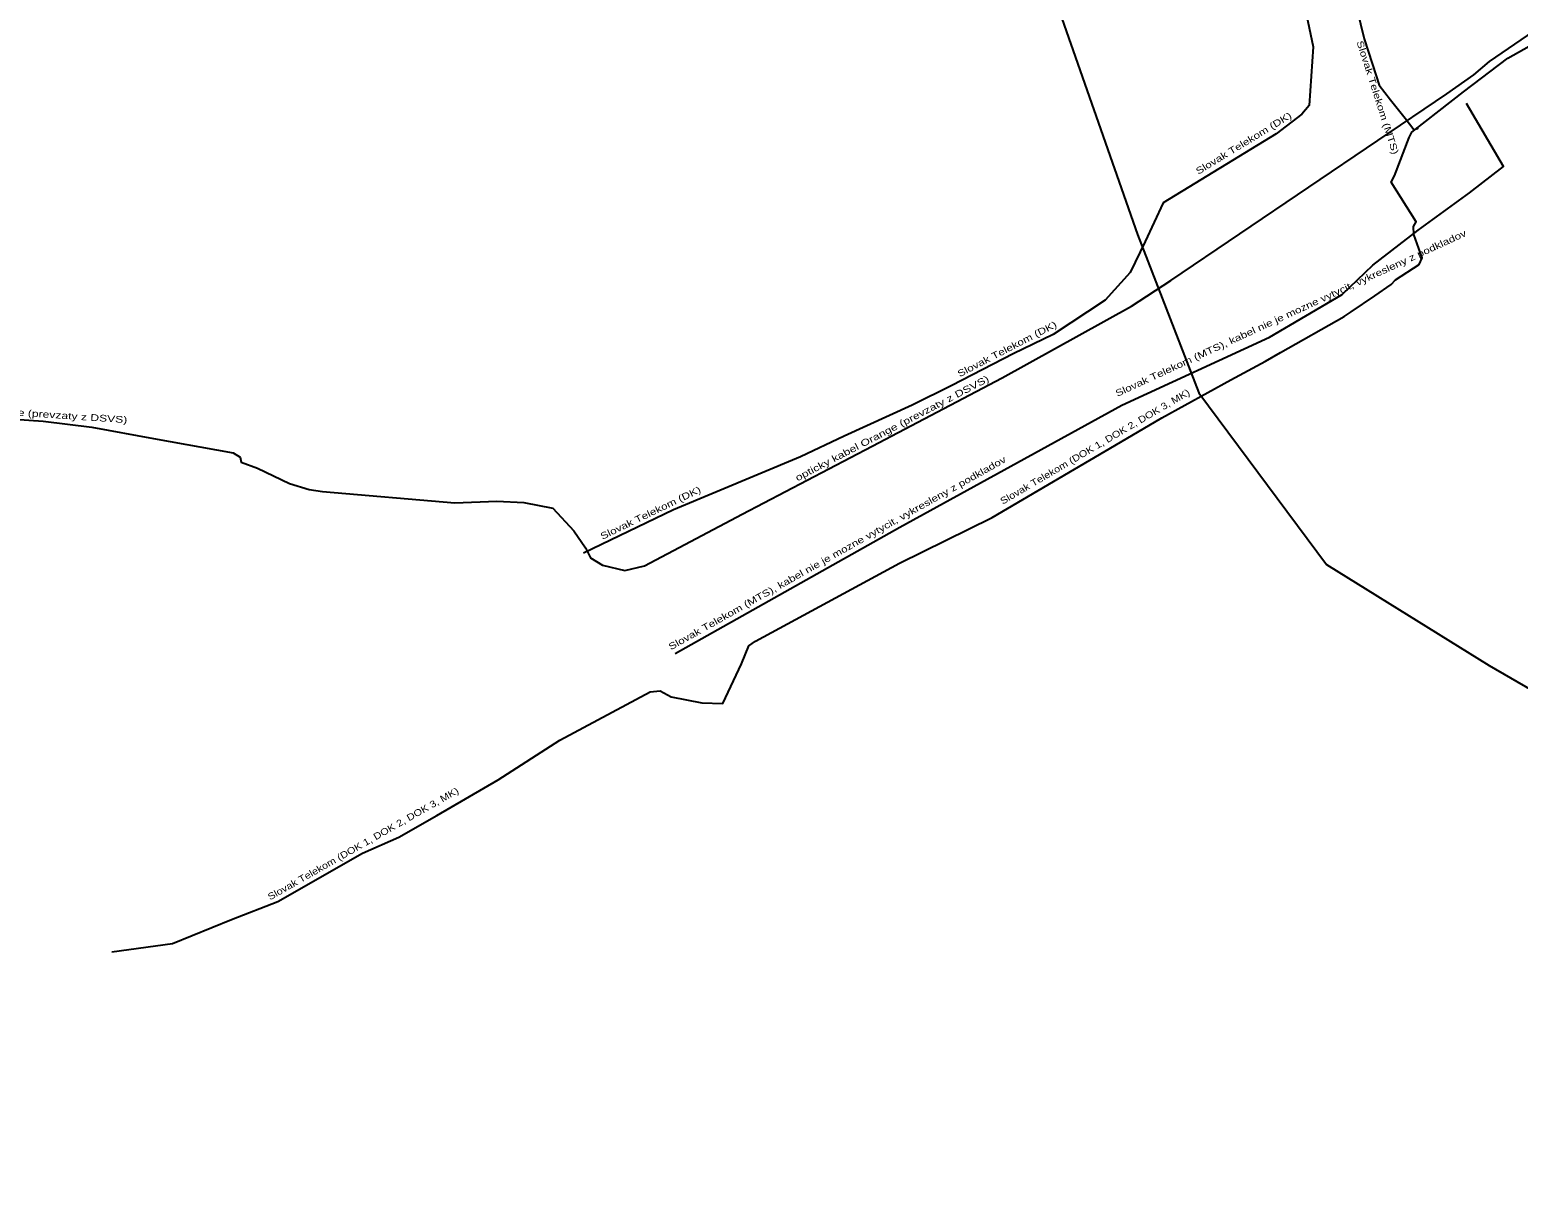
# Model space of a CAD drawing. Extents: x -347142 to -339829, y -1273273 to -1271592.
# Drawn here: x -344698.9 to -344255.5, y -1273148.9 to -1272799.8 of the extents above; entities that cross this region are included whole.
import ezdxf

# ---------------------------------------------------------------- set-up
doc = ezdxf.new("R2010")
doc.units = 0
doc.header["$LTSCALE"] = 0.8
doc.layers.add('12', color=7, linetype='Continuous', lineweight=25)
doc.layers.add('22', color=7, linetype='Continuous', lineweight=25)
doc.layers.add('60', color=7, linetype='Continuous')

msp = doc.modelspace()

# ---------------------------------------------------------------- linework, layer by layer
at = {"layer": '12'}
for points in [[(-344271.831, -1272818.294), (-344258.591, -1272808.281), (-344242.704, -1272799.364), (-344235.379, -1272795.973), (-344221.267, -1272789.708), (-344218.4, -1272789.31), (-344208.14, -1272785.32), (-344194.24, -1272777.61), (-344191.31, -1272775.79), (-344187.89, -1272774.89), (-344170.25, -1272766.73), (-344168.62, -1272766.17), (-344166.41, -1272763.47), (-344163.05, -1272757.92), (-344160.29, -1272755.14), (-344158.55, -1272752.86), (-344143.07, -1272746.54), (-344091.18, -1272725.26), (-344071.88, -1272718.87), (-344052.18, -1272714.83), (-344011.24, -1272707.08), (-343959.6, -1272696.52)], [(-344320.121, -1272730.722), (-344319.37, -1272791.73), (-344316.55, -1272804.95), (-344317.76, -1272822.35), (-344319.92, -1272824.93), (-344327.583, -1272830.826), (-344361.269, -1272851.364), (-344366.599, -1272862.9), (-344371.045, -1272872.147), (-344378.526, -1272880.321), (-344393.991, -1272890.603), (-344405.922, -1272896.307), (-344424.25, -1272905.789), (-344436.014, -1272911.561), (-344456.234, -1272920.837), (-344469.296, -1272926.962), (-344507.099, -1272942.748), (-344533.926, -1272955.693)], [(-344303.548, -1272793.626), (-344301.344, -1272802.563), (-344297.82, -1272813.591), (-344296.927, -1272816.365), (-344293.574, -1272820.714), (-344289.16, -1272826.123), (-344286.581, -1272829.572), (-344285.395, -1272829.221), (-344285.652, -1272828.866)], [(-344638.31, -1272925.81), (-344636.14, -1272927.06), (-344635.92, -1272928.62), (-344631.06, -1272930.35), (-344621.52, -1272934.93), (-344615.61, -1272936.72), (-344611.71, -1272937.35), (-344572.2, -1272940.66), (-344559.76, -1272940.18), (-344551.71, -1272940.59), (-344543.03, -1272942.28), (-344536.77, -1272949.01), (-344533.33, -1272954.12), (-344531.82, -1272957.06), (-344528.24, -1272959.28), (-344521.6, -1272960.86), (-344515.76, -1272959.48), (-344486.65, -1272944.03), (-344447.94, -1272923.81), (-344409.18, -1272903.5), (-344370.68, -1272882.1), (-344358.99, -1272874.45), (-344276.75, -1272818.93), (-344268.68, -1272813.26), (-344264.07, -1272809.27), (-344250.84, -1272800.26)], [(-344674.44, -1273074.37), (-344656.31, -1273071.93), (-344638.73, -1273064.75), (-344624.98, -1273059.38), (-344599.73, -1273045.01), (-344588.88, -1273040.2), (-344577.58, -1273033.81), (-344559.383, -1273023.116), (-344540.936, -1273011.329), (-344514.051, -1272996.91), (-344511.09, -1272996.647), (-344507.801, -1272998.466), (-344498.648, -1273000.193), (-344492.406, -1273000.41), (-344486.842, -1272988.574), (-344484.659, -1272983.297), (-344482.706, -1272981.903), (-344439.813, -1272958.659), (-344412.226, -1272945.065), (-344373.98, -1272922.604), (-344361.615, -1272915.338), (-344341.095, -1272904.058), (-344330.789, -1272898.475), (-344326.342, -1272895.893), (-344307.373, -1272885.172), (-344305.233, -1272883.846), (-344298.182, -1272879.064), (-344293.294, -1272875.645), (-344292.064, -1272874.295), (-344284.974, -1272869.701), (-344284.119, -1272867.734), (-344286.547, -1272860.796), (-344286.732, -1272858.418), (-344285.921, -1272856.98), (-344293.332, -1272845.169), (-344292.337, -1272843.316), (-344287.945, -1272831.887), (-344287.189, -1272830.301), (-344279.004, -1272823.97), (-344271.831, -1272818.294)], [(-344737.61, -1272913.41), (-344694.9, -1272916.32), (-344680.39, -1272918.19), (-344661.98, -1272921.57), (-344638.31, -1272925.81)]]:
    msp.add_lwpolyline(points, dxfattribs=at)
at = {"layer": '22'}
for points in [[(-345382.901, -1271994.853), (-345220.625, -1272191.708), (-345080.647, -1272378.657), (-345014.993, -1272391.038), (-344827.942, -1272409.609), (-344699.107, -1272452.241), (-344637.526, -1272474.503), (-344496.018, -1272530.814), (-344460.641, -1272598.91), (-344368.924, -1272860.82), (-344350.58, -1272907.963), (-344312.583, -1272959.036), (-344264.103, -1272989.155), (-343987.64, -1273148.92)], [(-344506.658, -1272985.535), (-344439.643, -1272947.878), (-344373.605, -1272911.635), (-344329.556, -1272891.351), (-344307.979, -1272878.693), (-344298.809, -1272869.916), (-344285.297, -1272859.511), (-344269.96, -1272848.342), (-344259.882, -1272840.567), (-344270.906, -1272821.743)]]:
    msp.add_lwpolyline(points, dxfattribs=at)

# ---------------------------------------------------------------- texts
at = {"layer": '60'}
for s, rotation, width, p in [('Slovak Telekom (MTS)', 287.739, 1.3, (-344303.678, -1272803.447)), ('Slovak Telekom (DK)', 31.398, 1.3, (-344350.773, -1272843.026)), ('Slovak Telekom (MTS), kabel nie je mozne vytycit, vykresleny z podkladov', 24.752, 1.3, (-344374.908, -1272909.138)), ('Slovak Telekom (DK)', 27.33, 1.3, (-344421.883, -1272903.312)), ('opticky kabel Orange (prevzaty z DSVS)', 27.559, 1.35, (-344470.172, -1272934.303)), ('Slovak Telekom (DOK 1, DOK 2, DOK 3, MK)', 30.424, 1.2, (-344409.051, -1272941.253)), ('opticky kabel Orange (prevzaty z DSVS)', 356.093, 1.35, (-344734.332, -1272912.569)), ('Slovak Telekom (MTS), kabel nie je mozne vytycit, vykresleny z podkladov', 29.335, 1.3, (-344507.879, -1272984.607)), ('Slovak Telekom (DK)', 25.783, 1.3, (-344528.294, -1272951.716)), ('Slovak Telekom (DOK 1, DOK 2, DOK 3, MK)', 29.622, 1.2, (-344627.27, -1273059.077))]:
    msp.add_text(s, height=2, rotation=rotation, dxfattribs=dict(at, width=width)).set_placement(p)

doc.saveas('drawing.dxf')
